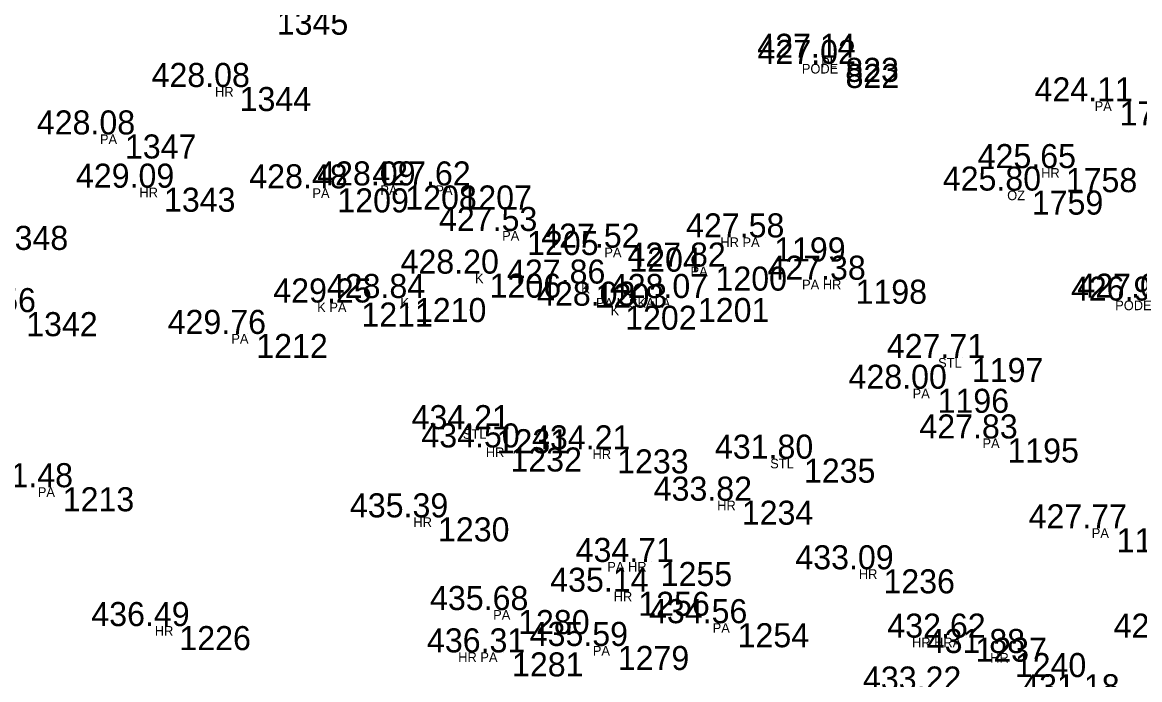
# Model space of a CAD drawing. Extents: x -639390 to -639075, y -1138747 to -1138358.
# Drawn here: x -639236.35 to -639201.49, y -1138624.12 to -1138603.62 of the extents above; entities that cross this region are included whole.
import ezdxf

# ---------------------------------------------------------------- set-up
doc = ezdxf.new("R2010")
doc.units = 0
for name, color, linetype in [('Vrstva 11', 7, 'Continuous'), ('Vrstva 12', 7, 'Continuous'), ('Vrstva 13', 7, 'Continuous'), ('Vrstva 57', 7, 'Continuous')]:
    doc.layers.add(name, color=color, linetype=linetype)

msp = doc.modelspace()

# ---------------------------------------------------------------- linework, layer by layer
at = {"layer": 'Vrstva 11'}
for p, q in [((-639210.95, -1138604.73), (-639210.95, -1138604.73)), ((-639210.94, -1138604.92), (-639210.94, -1138604.92)), ((-639229.85, -1138605.64), (-639229.85, -1138605.64)), ((-639202.39, -1138606.09), (-639202.39, -1138606.09)), ((-639233.43, -1138607.12), (-639233.43, -1138607.12)), ((-639204.07, -1138608.17), (-639204.07, -1138608.17)), ((-639232.21, -1138608.78), (-639232.21, -1138608.78)), ((-639226.8, -1138608.8), (-639226.8, -1138608.8)), ((-639224.68, -1138608.71), (-639224.68, -1138608.71)), ((-639222.96, -1138608.71), (-639222.96, -1138608.71)), ((-639205.13, -1138608.87), (-639205.13, -1138608.87)), ((-639220.88, -1138610.13), (-639220.88, -1138610.13)), ((-639213.17, -1138610.33), (-639213.17, -1138610.33)), ((-639217.69, -1138610.65), (-639217.69, -1138610.65)), ((-639215, -1138611.24), (-639215, -1138611.24)), ((-639222.05, -1138611.46), (-639222.05, -1138611.46)), ((-639218.74, -1138611.77), (-639218.74, -1138611.77)), ((-639210.63, -1138611.65), (-639210.63, -1138611.65)), ((-639224.38, -1138612.22), (-639224.38, -1138612.22)), ((-639215.55, -1138612.22), (-639215.55, -1138612.22)), ((-639226.05, -1138612.36), (-639226.05, -1138612.36)), ((-639217.82, -1138612.46), (-639217.82, -1138612.46)), ((-639229.33, -1138613.34), (-639229.33, -1138613.34)), ((-639207, -1138614.09), (-639207, -1138614.09)), ((-639208.07, -1138615.05), (-639208.07, -1138615.05)), ((-639221.83, -1138616.31), (-639221.83, -1138616.31)), ((-639205.89, -1138616.6), (-639205.89, -1138616.6)), ((-639221.4, -1138616.88), (-639221.4, -1138616.88)), ((-639218.07, -1138616.94), (-639218.07, -1138616.94)), ((-639212.24, -1138617.23), (-639212.24, -1138617.23)), ((-639235.37, -1138618.12), (-639235.37, -1138618.12)), ((-639214.18, -1138618.54), (-639214.18, -1138618.54)), ((-639223.66, -1138619.06), (-639223.66, -1138619.06)), ((-639202.48, -1138619.4), (-639202.48, -1138619.4)), ((-639216.71, -1138620.45), (-639216.71, -1138620.45)), ((-639209.76, -1138620.68), (-639209.76, -1138620.68)), ((-639217.41, -1138621.38), (-639217.41, -1138621.38)), ((-639221.16, -1138621.95), (-639221.16, -1138621.95)), ((-639214.31, -1138622.36), (-639214.31, -1138622.36)), ((-639231.73, -1138622.45), (-639231.73, -1138622.45)), ((-639218.05, -1138623.07), (-639218.05, -1138623.07)), ((-639206.89, -1138622.81), (-639206.89, -1138622.81)), ((-639221.35, -1138623.27), (-639221.35, -1138623.27)), ((-639205.66, -1138623.29), (-639205.66, -1138623.29))]:
    msp.add_line(p, q, dxfattribs=at)

# ---------------------------------------------------------------- texts
at = {"layer": 'Vrstva 12'}
for s, p in [('427.14 ', (-639213.419, -1138604.73)), ('427.02 ', (-639213.409, -1138604.92)), ('428.08 ', (-639232.319, -1138605.64)), ('424.11 ', (-639204.765, -1138606.09)), ('428.08 ', (-639235.899, -1138607.12)), ('425.65 ', (-639206.54, -1138608.17)), ('429.09 ', (-639234.679, -1138608.78)), ('428.48 ', (-639229.269, -1138608.8)), ('428.09 ', (-639227.149, -1138608.71)), ('427.62 ', (-639225.429, -1138608.71)), ('425.80 ', (-639207.629, -1138608.87)), ('427.53 ', (-639223.349, -1138610.13)), ('427.58 ', (-639215.639, -1138610.33)), ('427.52 ', (-639220.159, -1138610.65)), ('427.82 ', (-639217.469, -1138611.24)), ('428.20 ', (-639224.549, -1138611.46)), ('427.38 ', (-639213.099, -1138611.65)), ('427.86 ', (-639221.226, -1138611.77)), ('429.25 ', (-639228.52, -1138612.36)), ('428.84 ', (-639226.849, -1138612.22)), ('428.07 ', (-639218.019, -1138612.22)), ('426.98 ', (-639203.629, -1138612.3)), ('427.09 ', (-639203.429, -1138612.21)), ('430.56 ', (-639238.996, -1138612.66)), ('428.03 ', (-639220.289, -1138612.46)), ('429.76 ', (-639231.816, -1138613.34)), ('427.71 ', (-639209.375, -1138614.09)), ('428.00 ', (-639210.569, -1138615.05)), ('434.21 ', (-639224.205, -1138616.31)), ('434.50 ', (-639223.899, -1138616.88)), ('427.83 ', (-639208.359, -1138616.6)), ('434.21 ', (-639220.445, -1138616.94)), ('431.80 ', (-639214.739, -1138617.23)), ('431.48 ', (-639237.839, -1138618.12)), ('433.82 ', (-639216.649, -1138618.54)), ('435.39 ', (-639226.129, -1138619.06)), ('427.77 ', (-639204.949, -1138619.4)), ('434.71 ', (-639219.085, -1138620.45)), ('433.09 ', (-639212.229, -1138620.68)), ('435.14 ', (-639219.879, -1138621.38)), ('435.68 ', (-639223.629, -1138621.95)), ('436.49 ', (-639234.199, -1138622.45)), ('434.56 ', (-639216.796, -1138622.36)), ('432.62 ', (-639209.359, -1138622.81)), ('428.16 ', (-639202.296, -1138622.81)), ('435.59 ', (-639220.519, -1138623.07)), ('436.31 ', (-639223.725, -1138623.27)), ('431.88 ', (-639208.129, -1138623.29)), ('433.22 ', (-639210.119, -1138624.46)), ('431.18 ', (-639205.179, -1138624.7))]:
    msp.add_text(s, height=0.75, dxfattribs=at).set_placement(p)
at = {"layer": 'Vrstva 13'}
for s, p in [(' 1345', (-639228.69, -1138604.01)), (' 823', (-639210.95, -1138605.48)), (' 822', (-639210.94, -1138605.67)), (' 1344', (-639229.85, -1138606.39)), (' 1757', (-639202.39, -1138606.84)), (' 1347', (-639233.43, -1138607.87)), (' 1758', (-639204.07, -1138608.92)), (' 1343', (-639232.21, -1138609.53)), (' 1209', (-639226.8, -1138609.55)), (' 1208', (-639224.68, -1138609.46)), (' 1207', (-639222.96, -1138609.46)), (' 1759', (-639205.13, -1138609.62)), (' 1348', (-639237.43, -1138610.72)), (' 1205', (-639220.88, -1138610.88)), (' 1199', (-639213.17, -1138611.08)), (' 1204', (-639217.69, -1138611.4)), (' 1200', (-639215, -1138611.99)), (' 1206', (-639222.05, -1138612.21)), (' 1203', (-639218.74, -1138612.52)), (' 1198', (-639210.63, -1138612.4)), (' 1210', (-639224.38, -1138612.97)), (' 1201', (-639215.55, -1138612.97)), (' 1342', (-639236.51, -1138613.41)), (' 1211', (-639226.05, -1138613.11)), (' 1202', (-639217.82, -1138613.21)), (' 1212', (-639229.33, -1138614.09)), (' 1197', (-639207, -1138614.84)), (' 1196', (-639208.07, -1138615.8)), (' 1231', (-639221.83, -1138617.06)), (' 1195', (-639205.89, -1138617.35)), (' 1232', (-639221.4, -1138617.63)), (' 1233', (-639218.07, -1138617.69)), (' 1235', (-639212.24, -1138617.98)), (' 1213', (-639235.37, -1138618.87)), (' 1234', (-639214.18, -1138619.29)), (' 1230', (-639223.66, -1138619.81)), (' 1194', (-639202.48, -1138620.15)), (' 1255', (-639216.71, -1138621.2)), (' 1236', (-639209.76, -1138621.43)), (' 1256', (-639217.41, -1138622.13)), (' 1280', (-639221.16, -1138622.7)), (' 1254', (-639214.31, -1138623.11)), (' 1226', (-639231.73, -1138623.2)), (' 1279', (-639218.05, -1138623.82)), (' 1237', (-639206.89, -1138623.56)), (' 1281', (-639221.35, -1138624.02)), (' 1240', (-639205.66, -1138624.04))]:
    msp.add_text(s, height=0.75, dxfattribs=at).set_placement(p)
at = {"layer": 'Vrstva 57'}
for s, p in [('PODE', (-639212.027, -1138605.22)), ('PL', (-639211.425, -1138605.03)), ('HR', (-639230.339, -1138605.94)), ('PA', (-639202.89, -1138606.39)), ('PA', (-639233.93, -1138607.42)), ('HR', (-639204.559, -1138608.47)), ('HR', (-639232.699, -1138609.08)), ('PA', (-639227.3, -1138609.1)), ('PA', (-639225.18, -1138609.01)), ('PA', (-639223.46, -1138609.01)), ('OZ', (-639205.619, -1138609.17)), ('PA', (-639221.38, -1138610.43)), ('HR PA', (-639214.57, -1138610.63)), ('PA', (-639218.19, -1138610.95)), ('PA', (-639215.5, -1138611.54)), ('K', (-639222.225, -1138611.76)), ('K', (-639218.915, -1138612.07)), ('PA HR', (-639212.019, -1138611.95)), ('K', (-639224.555, -1138612.52)), ('PA K SKALA', (-639218.45, -1138612.52)), ('PODE', (-639202.248, -1138612.6)), ('K PA', (-639227.15, -1138612.66)), ('K', (-639217.995, -1138612.76)), ('PA', (-639229.83, -1138613.64)), ('STL', (-639207.775, -1138614.39)), ('PA', (-639208.57, -1138615.35)), ('STL', (-639222.605, -1138616.61)), ('PA', (-639206.39, -1138616.9)), ('HR', (-639221.889, -1138617.18)), ('HR', (-639218.559, -1138617.24)), ('STL', (-639213.015, -1138617.53)), ('PA', (-639235.87, -1138618.42)), ('HR', (-639214.669, -1138618.84)), ('HR', (-639224.149, -1138619.36)), ('PA', (-639202.98, -1138619.7)), ('PA HR', (-639218.099, -1138620.75)), ('HR', (-639210.249, -1138620.98)), ('HR', (-639217.899, -1138621.68)), ('PA', (-639221.66, -1138622.25)), ('PA', (-639214.81, -1138622.66)), ('HR', (-639232.219, -1138622.75)), ('PA', (-639218.55, -1138623.37)), ('HR HRA', (-639208.59, -1138623.11)), ('HR PA', (-639222.75, -1138623.57)), ('HR', (-639206.149, -1138623.59))]:
    msp.add_text(s, height=0.3, dxfattribs=at).set_placement(p)

doc.saveas('drawing.dxf')
